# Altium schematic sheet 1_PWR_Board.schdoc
size 254 x 203 mm; Symbol: Altium_A; Device: Altium_A; SheetNumber: 1; SheetTotal: 5
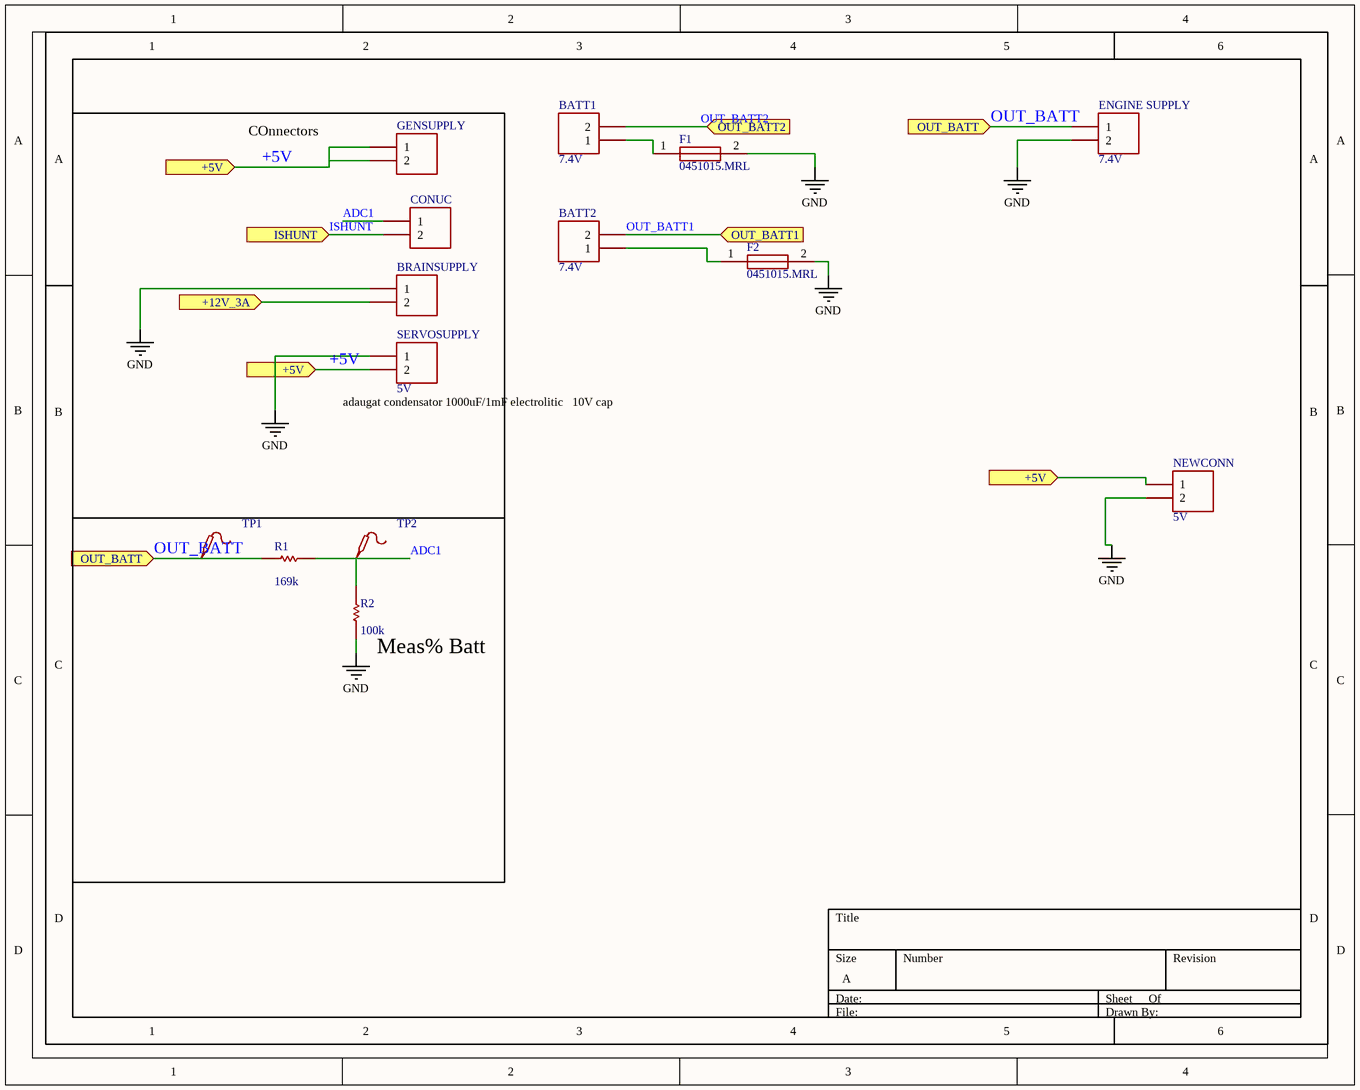
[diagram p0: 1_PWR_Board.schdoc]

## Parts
BATT1  7.4V  (value not drawn)
BATT2  7.4V  (value not drawn)
BRAINSUPPLY  6.1V-7.4V  [1704498]  (value not drawn)
CONUC  6.1V-7.4V  [1704498]  (value not drawn)
ENGINE_SUPPLY  7.4V  (value not drawn)
F1  0451015.MRL  [FUSC6127X294N]  (value not drawn)
F2  0451015.MRL  [FUSC6127X294N]  (value not drawn)
GENSUPPLY  6.1V-7.4V  [1704498]  (value not drawn)
NEWCONN  5V  [1704498]  (value not drawn)
R1  value 169k  [R0603_NEW]  (hidden comment: MCR03..PFX1051)
R2  value 100k  [R0603_NEW]  (hidden comment: MCR03...PFX7680)
SERVOSUPPLY  5V  [1704498]  (value not drawn)
TP1  Test-Point  [Test-Point-0.5mm]  (value not drawn)
TP2  Test-Point  [Test-Point-0.5mm]  (value not drawn)

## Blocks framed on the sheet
COnnectors: BRAINSUPPLY CONUC GENSUPPLY SERVOSUPPLY
Meas% Batt: R1 R2 TP1 TP2

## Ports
+5V (in), +12V_3A (in), ISHUNT (in), OUT_BATT1 (in), OUT_BATT2 (in), OUT_BATT (in)

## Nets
GND: BRAINSUPPLY.1 ENGINE_SUPPLY.2 F1.2 F2.2 NEWCONN.2 R2.2 SERVOSUPPLY.1
+5V: GENSUPPLY.1 GENSUPPLY.2 NEWCONN.1 SERVOSUPPLY.2 ; port +5V
+12V_3A: BRAINSUPPLY.2 ; port +12V_3A
ADC1: CONUC.1 R1.1 R2.1 TP2.1
ISHUNT: CONUC.2 ; port ISHUNT
OUT_BATT: ENGINE_SUPPLY.1 R1.2 TP1.1 ; port OUT_BATT
OUT_BATT1: BATT2.2 ; port OUT_BATT1
OUT_BATT2: BATT1.2 ; port OUT_BATT2
NetBATT1_1: BATT1.1 F1.1
NetBATT2_1: BATT2.1 F2.1

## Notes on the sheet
- (near SERVOSUPPLY) adaugat condensator 1000uF/1mF electrolitic   10V cap

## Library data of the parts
BATT1 BATT2 ENGINE_SUPPLY NEWCONN = 7.4V: 2 Holes; Symbol: Header 2; Origin Footprint 2: HDR1X2; Add into BOM: yes; Origin Footprint 1: PCBComponent_1 - duplicate
BRAINSUPPLY CONUC GENSUPPLY = 6.1V-7.4V: Header, 2-Pin; Symbol: Header 2; Origin Footprint 2: HDR1X2; Add into BOM: yes; Origin Footprint 1: TB002V50002BE
F1 F2 = 0451015.MRL: Fuse; Manufacturer_Name: LITTELFUSE; Add into BOM: yes
R1 = MCR03..PFX1051: Resistor; Symbol: Res1; Origin Footprint 2: AXIAL-0.3; Add into BOM: yes; Origin Footprint 1: RESC1608X55N
R2 = MCR03...PFX7680: Resistor; Symbol: Res1; Origin Footprint 2: AXIAL-0.3; Add into BOM: yes; Origin Footprint 1: RESC1608X55N
SERVOSUPPLY = 5V: Header, 2-Pin; Symbol: Header 2; Origin Footprint 2: HDR1X2; Add into BOM: yes; Origin Footprint 1: TB002V50002BE
TP1 TP2 = Test-Point: Test Point 测试点; Add into BOM: yes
